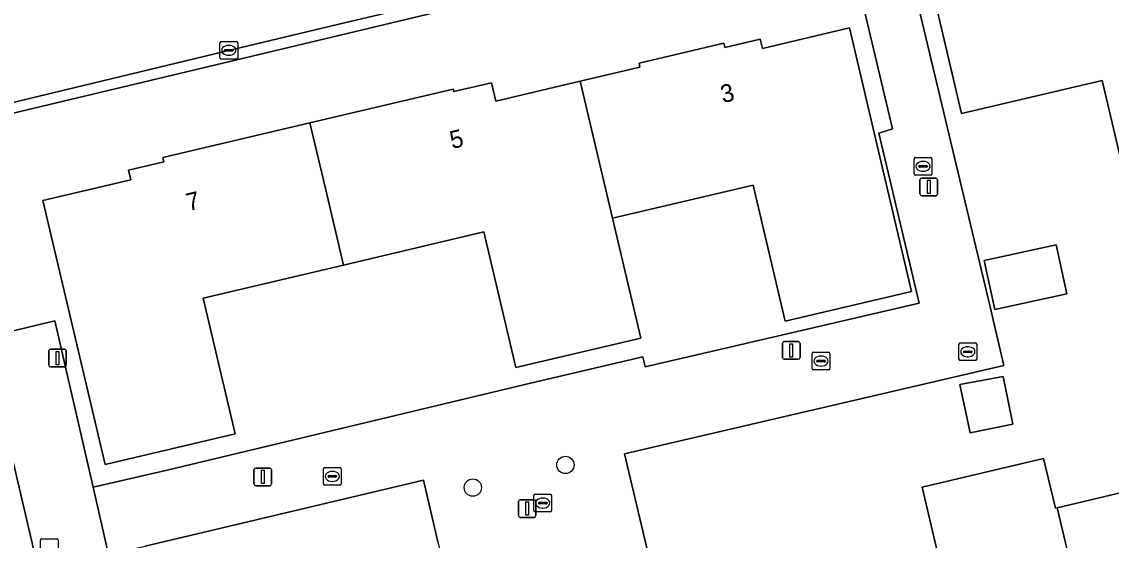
# Model space of a CAD drawing. Extents: x 157648 to 158502, y 379212 to 380938.
# Drawn here: x 158221.4 to 158282.9, y 380560.8 to 380590 of the extents above; entities that cross this region are included whole.
import ezdxf

# ---------------------------------------------------------------- set-up
doc = ezdxf.new("R2010")
doc.units = 0
for name, color, linetype in [('IMGEO_Boom', 7, 'Continuous'), ('IMGEO_Erf', 7, 'Continuous'), ('IMGEO_Groenvoorziening', 7, 'Continuous'), ('IMGEO_Hek', 7, 'Continuous'), ('IMGEO_Kolk', 7, 'Continuous'), ('IMGEO_Lichtmast', 7, 'Continuous'), ('IMGEO_Pand', 7, 'Continuous'), ('IMGEO_Pand_nummerreeks', 7, 'Continuous'), ('IMGEO_Rijbaan_lokaal_open', 7, 'Continuous'), ('IMGEO_Rioolput', 7, 'Continuous'), ('IMGEO_Voetpad_open', 7, 'Continuous')]:
    doc.layers.add(name, color=color, linetype=linetype)

msp = doc.modelspace()

# ---------------------------------------------------------------- linework, layer by layer
at = {"layer": 'IMGEO_Boom'}
for centre in [(158252.077, 380565.022), (158246.852, 380563.739)]:
    msp.add_circle(centre, 0.489, dxfattribs=at)
at = {"layer": 'IMGEO_Erf'}
for points in [[(158270.622, 380596.741), (158276.052, 380573.949), (158276.091, 380573.783), (158276.819, 380570.638), (158255.412, 380565.654), (158257.404, 380557.232)], [(158272.21, 380563.77), (158279.07, 380565.389), (158279.733, 380562.579), (158279.84, 380562.604), (158287.75, 380564.472)], [(158244.869, 380560.687), (158244.059, 380564.165), (158228.361, 380560.43)], [(158274.045, 380555.997), (158272.21, 380563.77)]]:
    msp.add_lwpolyline(points, dxfattribs=at)
for points in [[(158272.045, 380574.154), (158269.772, 380583.761), (158270.53, 380584.007), (158267.677, 380596.065), (158220.427, 380584.764), (158218.078, 380583.925), (158220.689, 380572.538), (158223.255, 380573.155), (158225.417, 380563.757), (158229.59, 380564.718), (158250.109, 380569.646), (158256.438, 380571.128), (158256.573, 380570.551)], [(158284.202, 380578.996), (158282.375, 380586.733), (158274.437, 380584.859), (158272.544, 380592.878), (158280.783, 380594.822), (158280.817, 380594.677), (158283.016, 380595.196), (158283.254, 380594.187), (158287.998, 380595.307), (158291.445, 380580.706), (158292.253, 380577.282), (158285.011, 380575.572)], [(158239.55, 380576.304), (158231.631, 380574.435), (158233.439, 380566.777), (158226.098, 380565.044), (158222.578, 380579.955), (158227.549, 380581.128), (158227.421, 380581.673), (158229.416, 380582.144), (158229.361, 380582.375), (158237.654, 380584.333), (158245.747, 380586.243), (158245.78, 380586.102), (158247.903, 380586.603), (158248.148, 380585.565), (158252.908, 380586.688), (158256.283, 380587.485), (158256.231, 380587.702), (158261.024, 380588.833), (158261.08, 380588.594), (158263.072, 380589.064), (158263.195, 380588.541), (158268.105, 380589.7), (158271.618, 380574.82), (158264.489, 380573.137), (158262.674, 380580.826), (158254.728, 380578.95), (158256.327, 380572.177), (158249.279, 380570.513), (158247.47, 380578.174)], [(158276.308, 380573.795), (158275.704, 380576.559), (158279.772, 380577.447), (158280.376, 380574.683)], [(158274.34, 380569.567), (158276.779, 380570.013), (158277.327, 380567.32), (158274.927, 380566.836)]]:
    msp.add_lwpolyline(points, close=True, dxfattribs=at)
at = {"layer": 'IMGEO_Groenvoorziening'}
msp.add_lwpolyline([(158208.994, 380577.47), (158206.036, 380574.234), (158216.938, 380564.64), (158218.496, 380557.919), (158222.404, 380558.759), (158219.876, 380569.535)], close=True, dxfattribs=at)
at = {"layer": 'IMGEO_Hek'}
for points in [[(158276.052, 380573.949), (158276.091, 380573.783)], [(158276.091, 380573.783), (158276.819, 380570.638)], [(158229.59, 380564.718), (158250.109, 380569.646)], [(158228.361, 380560.43), (158244.059, 380564.165), (158244.869, 380560.687)]]:
    msp.add_lwpolyline(points, dxfattribs=at)
at = {"layer": 'IMGEO_Kolk'}
for p, q in [((158232.578, 380588.007), (158232.578, 380588.859)), ((158232.653, 380588.933), (158233.505, 380588.933)), ((158232.837, 380588.427), (158232.837, 380588.439)), ((158233.275, 380588.39), (158232.877, 380588.39)), ((158232.88, 380588.476), (158233.278, 380588.476)), ((158233.066, 380588.713), (158233.091, 380588.713)), ((158233.321, 380588.439), (158233.321, 380588.427)), ((158233.579, 380588.859), (158233.579, 380588.007)), ((158233.505, 380587.933), (158232.653, 380587.933)), ((158233.089, 380588.153), (158233.064, 380588.153)), ((158271.765, 380581.455), (158271.765, 380582.307)), ((158271.84, 380582.381), (158272.692, 380582.381)), ((158272.766, 380582.307), (158272.766, 380581.455)), ((158272.024, 380581.875), (158272.024, 380581.887)), ((158272.462, 380581.838), (158272.064, 380581.838)), ((158272.067, 380581.924), (158272.465, 380581.924)), ((158272.276, 380581.601), (158272.251, 380581.601)), ((158272.253, 380582.161), (158272.278, 380582.161)), ((158272.508, 380581.887), (158272.508, 380581.875)), ((158272.692, 380581.381), (158271.84, 380581.381)), ((158266.006, 380570.459), (158266.006, 380571.311)), ((158266.081, 380571.385), (158266.933, 380571.385)), ((158266.494, 380571.165), (158266.519, 380571.165)), ((158267.007, 380571.311), (158267.007, 380570.459)), ((158266.265, 380570.879), (158266.265, 380570.891)), ((158266.703, 380570.842), (158266.305, 380570.842)), ((158266.308, 380570.928), (158266.706, 380570.928)), ((158266.517, 380570.605), (158266.492, 380570.605)), ((158266.749, 380570.891), (158266.749, 380570.879)), ((158266.933, 380570.385), (158266.081, 380570.385)), ((158238.421, 380563.947), (158238.421, 380564.799)), ((158238.496, 380564.873), (158239.348, 380564.873)), ((158238.723, 380564.416), (158239.121, 380564.416)), ((158238.909, 380564.653), (158238.934, 380564.653)), ((158239.422, 380564.799), (158239.422, 380563.947)), ((158239.348, 380563.873), (158238.496, 380563.873)), ((158238.68, 380564.367), (158238.68, 380564.379)), ((158239.118, 380564.33), (158238.72, 380564.33)), ((158238.932, 380564.093), (158238.907, 380564.093)), ((158239.164, 380564.379), (158239.164, 380564.367)), ((158250.299, 380562.44), (158250.299, 380563.292)), ((158250.374, 380563.366), (158251.226, 380563.366)), ((158251.3, 380563.292), (158251.3, 380562.44)), ((158250.558, 380562.86), (158250.558, 380562.872)), ((158250.996, 380562.823), (158250.598, 380562.823)), ((158250.601, 380562.909), (158250.999, 380562.909)), ((158250.81, 380562.586), (158250.785, 380562.586)), ((158250.787, 380563.146), (158250.812, 380563.146)), ((158251.042, 380562.872), (158251.042, 380562.86)), ((158251.226, 380562.366), (158250.374, 380562.366)), ((158222.451, 380559.917), (158222.451, 380560.769)), ((158222.526, 380560.843), (158223.378, 380560.843)), ((158223.452, 380560.769), (158223.452, 380559.917))]:
    msp.add_line(p, q, dxfattribs=at)
for points in [[(158232.578, 380588.007), (158232.578, 380588.859)], [(158232.653, 380588.933), (158233.505, 380588.933)], [(158233.579, 380588.859), (158233.579, 380588.007)], [(158233.505, 380587.933), (158232.653, 380587.933)], [(158271.765, 380581.455), (158271.765, 380582.307)], [(158271.84, 380582.381), (158272.692, 380582.381)], [(158272.766, 380582.307), (158272.766, 380581.455)], [(158272.692, 380581.381), (158271.84, 380581.381)], [(158266.006, 380570.459), (158266.006, 380571.311)], [(158266.081, 380571.385), (158266.933, 380571.385)], [(158267.007, 380571.311), (158267.007, 380570.459)], [(158266.933, 380570.385), (158266.081, 380570.385)], [(158238.421, 380563.947), (158238.421, 380564.799)], [(158238.496, 380564.873), (158239.348, 380564.873)], [(158239.422, 380564.799), (158239.422, 380563.947)], [(158239.348, 380563.873), (158238.496, 380563.873)], [(158250.299, 380562.44), (158250.299, 380563.292)], [(158250.374, 380563.366), (158251.226, 380563.366)], [(158251.3, 380563.292), (158251.3, 380562.44)], [(158251.226, 380562.366), (158250.374, 380562.366)], [(158222.451, 380559.917), (158222.451, 380560.769)], [(158222.526, 380560.843), (158223.378, 380560.843)], [(158223.452, 380560.769), (158223.452, 380559.917)]]:
    msp.add_lwpolyline(points, dxfattribs=at)
for centre, radius, start, end in [((158232.655, 380588.857), 0.0765, 91.55205, 178.44795), ((158232.655, 380588.857), 0.0765, 91.55205, 178.44795), ((158232.877, 380588.436), 0.0403, 85.87752, 175.75265), ((158232.874, 380588.426), 0.0366, 178.93798, 274.71019), ((158233.278, 380588.433), 0.043, 264.86636, 352.45326), ((158233.282, 380588.438), 0.0386, 1.73085, 96.63898), ((158233.503, 380588.857), 0.0765, 1.55205, 88.44795), ((158233.503, 380588.857), 0.0765, 1.55205, 88.44795), ((158232.655, 380588.009), 0.0765, 181.55205, 268.44795), ((158232.655, 380588.009), 0.0765, 181.55205, 268.44795), ((158233.503, 380588.009), 0.0765, 271.55205, 358.44795), ((158233.503, 380588.009), 0.0765, 271.55205, 358.44795), ((158271.842, 380582.305), 0.0765, 91.55205, 178.44795), ((158271.842, 380582.305), 0.0765, 91.55205, 178.44795), ((158272.69, 380582.305), 0.0765, 1.55205, 88.44795), ((158272.69, 380582.305), 0.0765, 1.55205, 88.44795), ((158272.064, 380581.884), 0.0403, 85.87752, 175.75265), ((158272.061, 380581.874), 0.0366, 178.93798, 274.71019), ((158272.465, 380581.881), 0.043, 264.86636, 352.45326), ((158272.469, 380581.886), 0.0386, 1.73085, 96.63898), ((158271.842, 380581.457), 0.0765, 181.55205, 268.44795), ((158271.842, 380581.457), 0.0765, 181.55205, 268.44795), ((158272.69, 380581.457), 0.0765, 271.55205, 358.44795), ((158272.69, 380581.457), 0.0765, 271.55205, 358.44795), ((158266.083, 380571.309), 0.0765, 91.55205, 178.44795), ((158266.083, 380571.309), 0.0765, 91.55205, 178.44795), ((158266.931, 380571.309), 0.0765, 1.55205, 88.44795), ((158266.931, 380571.309), 0.0765, 1.55205, 88.44795), ((158266.305, 380570.888), 0.0403, 85.87752, 175.75265), ((158266.302, 380570.878), 0.0366, 178.93798, 274.71019), ((158266.706, 380570.885), 0.043, 264.86636, 352.45326), ((158266.71, 380570.89), 0.0386, 1.73085, 96.63898), ((158266.083, 380570.461), 0.0765, 181.55205, 268.44795), ((158266.083, 380570.461), 0.0765, 181.55205, 268.44795), ((158266.931, 380570.461), 0.0765, 271.55205, 358.44795), ((158266.931, 380570.461), 0.0765, 271.55205, 358.44795), ((158238.498, 380564.797), 0.0765, 91.55205, 178.44795), ((158238.498, 380564.797), 0.0765, 91.55205, 178.44795), ((158238.72, 380564.376), 0.0403, 85.87752, 175.75265), ((158239.125, 380564.378), 0.0386, 1.73085, 96.63898), ((158239.346, 380564.797), 0.0765, 1.55205, 88.44795), ((158239.346, 380564.797), 0.0765, 1.55205, 88.44795), ((158238.498, 380563.949), 0.0765, 181.55205, 268.44795), ((158238.498, 380563.949), 0.0765, 181.55205, 268.44795), ((158238.717, 380564.366), 0.0366, 178.93798, 274.71019), ((158239.121, 380564.373), 0.043, 264.86636, 352.45326), ((158239.346, 380563.949), 0.0765, 271.55205, 358.44795), ((158239.346, 380563.949), 0.0765, 271.55205, 358.44795), ((158250.376, 380563.29), 0.0765, 91.55205, 178.44795), ((158250.376, 380563.29), 0.0765, 91.55205, 178.44795), ((158251.224, 380563.29), 0.0765, 1.55205, 88.44795), ((158251.224, 380563.29), 0.0765, 1.55205, 88.44795), ((158250.598, 380562.869), 0.0403, 85.87752, 175.75265), ((158250.595, 380562.859), 0.0366, 178.93798, 274.71019), ((158250.999, 380562.866), 0.043, 264.86636, 352.45326), ((158251.003, 380562.871), 0.0386, 1.73085, 96.63898), ((158250.376, 380562.442), 0.0765, 181.55205, 268.44795), ((158250.376, 380562.442), 0.0765, 181.55205, 268.44795), ((158251.224, 380562.442), 0.0765, 271.55205, 358.44795), ((158251.224, 380562.442), 0.0765, 271.55205, 358.44795), ((158222.528, 380560.767), 0.0765, 91.55205, 178.44795), ((158222.528, 380560.767), 0.0765, 91.55205, 178.44795), ((158223.376, 380560.767), 0.0765, 1.55205, 88.44795), ((158223.376, 380560.767), 0.0765, 1.55205, 88.44795)]:
    msp.add_arc(centre, radius, start, end, dxfattribs=at)
for centre, major_axis, ratio, start_param, end_param in [((158233.065, 380588.433), (-0.387, 0.002), 0.722429, 4.712389, 7.853982), ((158233.09, 380588.433), (-0.39, 0.002), 0.717154, 1.570796, 4.712389), ((158272.252, 380581.881), (-0.387, 0.002), 0.722429, 4.712389, 7.853982), ((158272.277, 380581.881), (-0.39, 0.002), 0.717154, 1.570796, 4.712389), ((158266.493, 380570.885), (-0.387, 0.002), 0.722429, 4.712389, 7.853982), ((158266.518, 380570.885), (-0.39, 0.002), 0.717154, 1.570796, 4.712389), ((158238.908, 380564.373), (-0.387, 0.002), 0.722429, 4.712389, 7.853982), ((158238.933, 380564.373), (-0.39, 0.002), 0.717154, 1.570796, 4.712389), ((158250.786, 380562.866), (-0.387, 0.002), 0.722429, 4.712389, 7.853982), ((158250.811, 380562.866), (-0.39, 0.002), 0.717154, 1.570796, 4.712389)]:
    msp.add_ellipse(centre, major_axis=major_axis, ratio=ratio, start_param=start_param, end_param=end_param, dxfattribs=at)
at = {"layer": 'IMGEO_Lichtmast'}
for p, q in [((158272.086, 380580.322), (158272.086, 380581.122)), ((158272.086, 380581.122), (158272.086, 380580.322)), ((158272.186, 380581.222), (158272.976, 380581.222)), ((158272.976, 380581.222), (158272.186, 380581.222)), ((158273.076, 380581.122), (158273.076, 380580.322)), ((158273.076, 380580.322), (158273.076, 380581.122)), ((158272.976, 380580.222), (158272.186, 380580.222)), ((158272.186, 380580.222), (158272.976, 380580.222)), ((158264.331, 380571.085), (158264.331, 380571.885)), ((158264.331, 380571.885), (158264.331, 380571.085)), ((158264.431, 380571.985), (158265.221, 380571.985)), ((158265.221, 380571.985), (158264.431, 380571.985)), ((158265.321, 380571.885), (158265.321, 380571.085)), ((158265.321, 380571.085), (158265.321, 380571.885)), ((158222.914, 380570.655), (158222.914, 380571.455)), ((158222.914, 380571.455), (158222.914, 380570.655)), ((158223.014, 380571.555), (158223.804, 380571.555)), ((158223.804, 380571.555), (158223.014, 380571.555)), ((158223.904, 380571.455), (158223.904, 380570.655)), ((158223.904, 380570.655), (158223.904, 380571.455)), ((158223.804, 380570.555), (158223.014, 380570.555)), ((158223.014, 380570.555), (158223.804, 380570.555)), ((158265.221, 380570.985), (158264.431, 380570.985)), ((158264.431, 380570.985), (158265.221, 380570.985)), ((158234.498, 380563.944), (158234.498, 380564.744)), ((158234.498, 380564.744), (158234.498, 380563.944)), ((158234.598, 380564.844), (158235.388, 380564.844)), ((158235.388, 380564.844), (158234.598, 380564.844)), ((158235.488, 380564.744), (158235.488, 380563.944)), ((158235.488, 380563.944), (158235.488, 380564.744)), ((158235.388, 380563.844), (158234.598, 380563.844)), ((158234.598, 380563.844), (158235.388, 380563.844)), ((158249.424, 380562.156), (158249.424, 380562.956)), ((158249.424, 380562.956), (158249.424, 380562.156)), ((158249.524, 380563.056), (158250.314, 380563.056)), ((158250.314, 380563.056), (158249.524, 380563.056)), ((158250.414, 380562.956), (158250.414, 380562.156)), ((158250.414, 380562.156), (158250.414, 380562.956)), ((158250.314, 380562.056), (158249.524, 380562.056)), ((158249.524, 380562.056), (158250.314, 380562.056))]:
    msp.add_line(p, q, dxfattribs=at)
for points in [[(158272.506, 380581.097), (158272.656, 380581.097), (158272.656, 380580.347), (158272.506, 380580.347), (158272.506, 380581.097)], [(158264.751, 380571.86), (158264.901, 380571.86), (158264.901, 380571.11), (158264.751, 380571.11), (158264.751, 380571.86)], [(158223.334, 380571.43), (158223.484, 380571.43), (158223.484, 380570.68), (158223.334, 380570.68), (158223.334, 380571.43)], [(158234.918, 380564.719), (158235.068, 380564.719), (158235.068, 380563.969), (158234.918, 380563.969), (158234.918, 380564.719)], [(158249.844, 380562.931), (158249.994, 380562.931), (158249.994, 380562.181), (158249.844, 380562.181), (158249.844, 380562.931)]]:
    msp.add_lwpolyline(points, dxfattribs=at)
for centre, start, end in [((158272.186, 380581.122), 90, 180), ((158272.186, 380581.122), 90, 180), ((158272.976, 380581.122), 0, 90), ((158272.976, 380581.122), 360, 90), ((158272.186, 380580.322), 180, 270), ((158272.186, 380580.322), 180, 270), ((158272.976, 380580.322), 270, 0), ((158272.976, 380580.322), 270, 0), ((158264.431, 380571.885), 90, 180), ((158264.431, 380571.885), 90, 180), ((158265.221, 380571.885), 0, 90), ((158265.221, 380571.885), 360, 90), ((158223.014, 380571.455), 90, 180), ((158223.014, 380571.455), 90, 180), ((158223.804, 380571.455), 0, 90), ((158223.804, 380571.455), 360, 90), ((158223.014, 380570.655), 180, 270), ((158223.014, 380570.655), 180, 270), ((158223.804, 380570.655), 270, 0), ((158223.804, 380570.655), 270, 0), ((158264.431, 380571.085), 180, 270), ((158264.431, 380571.085), 180, 270), ((158265.221, 380571.085), 270, 0), ((158265.221, 380571.085), 270, 0), ((158234.598, 380564.744), 90, 180), ((158234.598, 380564.744), 90, 180), ((158235.388, 380564.744), 0, 90), ((158235.388, 380564.744), 360, 90), ((158234.598, 380563.944), 180, 270), ((158234.598, 380563.944), 180, 270), ((158235.388, 380563.944), 270, 0), ((158235.388, 380563.944), 270, 0), ((158249.524, 380562.956), 90, 180), ((158249.524, 380562.956), 90, 180), ((158250.314, 380562.956), 0, 90), ((158250.314, 380562.956), 360, 90), ((158249.524, 380562.156), 180, 270), ((158249.524, 380562.156), 180, 270), ((158250.314, 380562.156), 270, 0), ((158250.314, 380562.156), 270, 0)]:
    msp.add_arc(centre, 0.1, start, end, dxfattribs=at)
at = {"layer": 'IMGEO_Pand'}
for points in [[(158287.998, 380595.307), (158283.254, 380594.187), (158283.016, 380595.196), (158280.817, 380594.677), (158280.783, 380594.822), (158272.544, 380592.878), (158274.437, 380584.859), (158282.375, 380586.733), (158284.202, 380578.996), (158285.011, 380575.572), (158292.253, 380577.282), (158291.445, 380580.706)], [(158252.908, 380586.688), (158254.728, 380578.95), (158262.674, 380580.826), (158264.489, 380573.137), (158271.618, 380574.82), (158268.105, 380589.7), (158263.195, 380588.541), (158263.072, 380589.064), (158261.08, 380588.594), (158261.024, 380588.833), (158256.231, 380587.702), (158256.283, 380587.485)], [(158252.908, 380586.688), (158248.148, 380585.565), (158247.903, 380586.603), (158245.78, 380586.102), (158245.747, 380586.243), (158237.654, 380584.333), (158238.527, 380580.635), (158239.55, 380576.304), (158247.47, 380578.174), (158249.279, 380570.513), (158256.327, 380572.177), (158254.728, 380578.95)], [(158239.55, 380576.304), (158238.527, 380580.635), (158237.654, 380584.333), (158229.361, 380582.375), (158229.416, 380582.144), (158227.421, 380581.673), (158227.549, 380581.128), (158222.578, 380579.955), (158226.098, 380565.044), (158233.439, 380566.777), (158231.631, 380574.435)], [(158276.308, 380573.795), (158280.376, 380574.683), (158279.772, 380577.447), (158275.704, 380576.559)], [(158281.797, 380554.784), (158285.132, 380555.571), (158285.18, 380555.37), (158289.865, 380556.476), (158289.804, 380556.733), (158292.016, 380557.255), (158291.752, 380558.375), (158296.468, 380559.488), (158293.053, 380573.955), (158285.909, 380572.269), (158287.75, 380564.472), (158279.84, 380562.604), (158281.69, 380554.759)], [(158274.34, 380569.567), (158274.927, 380566.836), (158277.327, 380567.32), (158276.779, 380570.013)], [(158267.911, 380546.258), (158271.108, 380547.012), (158271.158, 380546.798), (158276.142, 380547.975), (158276.075, 380548.258), (158278.309, 380548.785), (158278.067, 380549.81), (158282.712, 380550.907), (158281.797, 380554.784), (158281.69, 380554.759), (158279.84, 380562.604), (158279.733, 380562.579), (158279.07, 380565.389), (158272.21, 380563.77), (158274.045, 380555.997), (158266.083, 380554.117)]]:
    msp.add_lwpolyline(points, close=True, dxfattribs=at)
at = {"layer": 'IMGEO_Rijbaan_lokaal_open'}
msp.add_lwpolyline([(158220.197, 380585.318), (158233.307, 380588.484), (158239.207, 380589.889), (158251.335, 380592.777), (158255.011, 380593.655), (158271.699, 380597.627)], dxfattribs=at)
at = {"layer": 'IMGEO_Rioolput'}
for p, q in [((158274.289, 380570.984), (158274.289, 380571.836)), ((158274.364, 380571.91), (158275.216, 380571.91)), ((158275.29, 380571.836), (158275.29, 380570.984)), ((158274.548, 380571.404), (158274.548, 380571.416)), ((158274.986, 380571.367), (158274.588, 380571.367)), ((158274.591, 380571.453), (158274.989, 380571.453)), ((158274.777, 380571.69), (158274.802, 380571.69)), ((158275.032, 380571.416), (158275.032, 380571.404)), ((158275.216, 380570.91), (158274.364, 380570.91)), ((158274.8, 380571.13), (158274.775, 380571.13))]:
    msp.add_line(p, q, dxfattribs=at)
for points in [[(158274.289, 380570.984), (158274.289, 380571.836)], [(158274.364, 380571.91), (158275.216, 380571.91)], [(158275.29, 380571.836), (158275.29, 380570.984)], [(158275.216, 380570.91), (158274.364, 380570.91)]]:
    msp.add_lwpolyline(points, dxfattribs=at)
for centre, radius, start, end in [((158274.366, 380571.834), 0.0765, 91.55205, 178.44795), ((158274.366, 380571.834), 0.0765, 91.55205, 178.44795), ((158275.214, 380571.834), 0.0765, 1.55205, 88.44795), ((158275.214, 380571.834), 0.0765, 1.55205, 88.44795), ((158274.588, 380571.413), 0.0403, 85.87752, 175.75265), ((158274.585, 380571.403), 0.0366, 178.93798, 274.71019), ((158274.989, 380571.41), 0.043, 264.86636, 352.45326), ((158274.993, 380571.415), 0.0386, 1.73085, 96.63898), ((158274.366, 380570.986), 0.0765, 181.55205, 268.44795), ((158274.366, 380570.986), 0.0765, 181.55205, 268.44795), ((158275.214, 380570.986), 0.0765, 271.55205, 358.44795), ((158275.214, 380570.986), 0.0765, 271.55205, 358.44795)]:
    msp.add_arc(centre, radius, start, end, dxfattribs=at)
for centre, major_axis, ratio, start_param, end_param in [((158274.776, 380571.41), (-0.387, 0.002), 0.722429, 4.712389, 7.853982), ((158274.801, 380571.41), (-0.39, 0.002), 0.717154, 1.570796, 4.712389)]:
    msp.add_ellipse(centre, major_axis=major_axis, ratio=ratio, start_param=start_param, end_param=end_param, dxfattribs=at)
at = {"layer": 'IMGEO_Voetpad_open'}
for points in [[(158267.677, 380596.065), (158270.622, 380596.741), (158275.52, 380597.895), (158275.397, 380598.476), (158271.699, 380597.627), (158255.011, 380593.655), (158251.335, 380592.777), (158239.207, 380589.889), (158233.307, 380588.484), (158220.197, 380585.318)], [(158217.925, 380584.488), (158218.078, 380583.925), (158220.427, 380584.764), (158267.677, 380596.065)], [(158230.238, 380543.354), (158226.289, 380559.958), (158225.417, 380563.757), (158223.255, 380573.155), (158220.689, 380572.538), (158218.078, 380583.925), (158217.925, 380584.488)], [(158209.549, 380578.944), (158208.577, 380577.884), (158208.994, 380577.47), (158219.876, 380569.535), (158222.404, 380558.759), (158218.496, 380557.919), (158228.061, 380517.741), (158228.842, 380514.468), (158229.701, 380510.871)]]:
    msp.add_lwpolyline(points, dxfattribs=at)
msp.add_lwpolyline([(158255.412, 380565.654), (158276.819, 380570.638), (158276.091, 380573.783), (158276.052, 380573.949), (158270.622, 380596.741), (158267.677, 380596.065), (158270.53, 380584.007), (158269.772, 380583.761), (158272.045, 380574.154), (158256.573, 380570.551), (158256.438, 380571.128), (158250.109, 380569.646), (158229.59, 380564.718), (158225.417, 380563.757), (158226.289, 380559.958), (158228.361, 380560.43), (158244.059, 380564.165), (158244.869, 380560.687), (158246.269, 380554.686), (158257.404, 380557.232)], close=True, dxfattribs=at)

# ---------------------------------------------------------------- texts
at = {"layer": 'IMGEO_Pand_nummerreeks'}
for s, rotation, p in [('3', 13.27716, (158260.962, 380585.448)), ('5', 13.28183, (158245.679, 380582.857)), ('7', 13.28183, (158230.8, 380579.345))]:
    msp.add_text(s, height=1, rotation=rotation, dxfattribs=at).set_placement(p)

doc.saveas('drawing.dxf')
